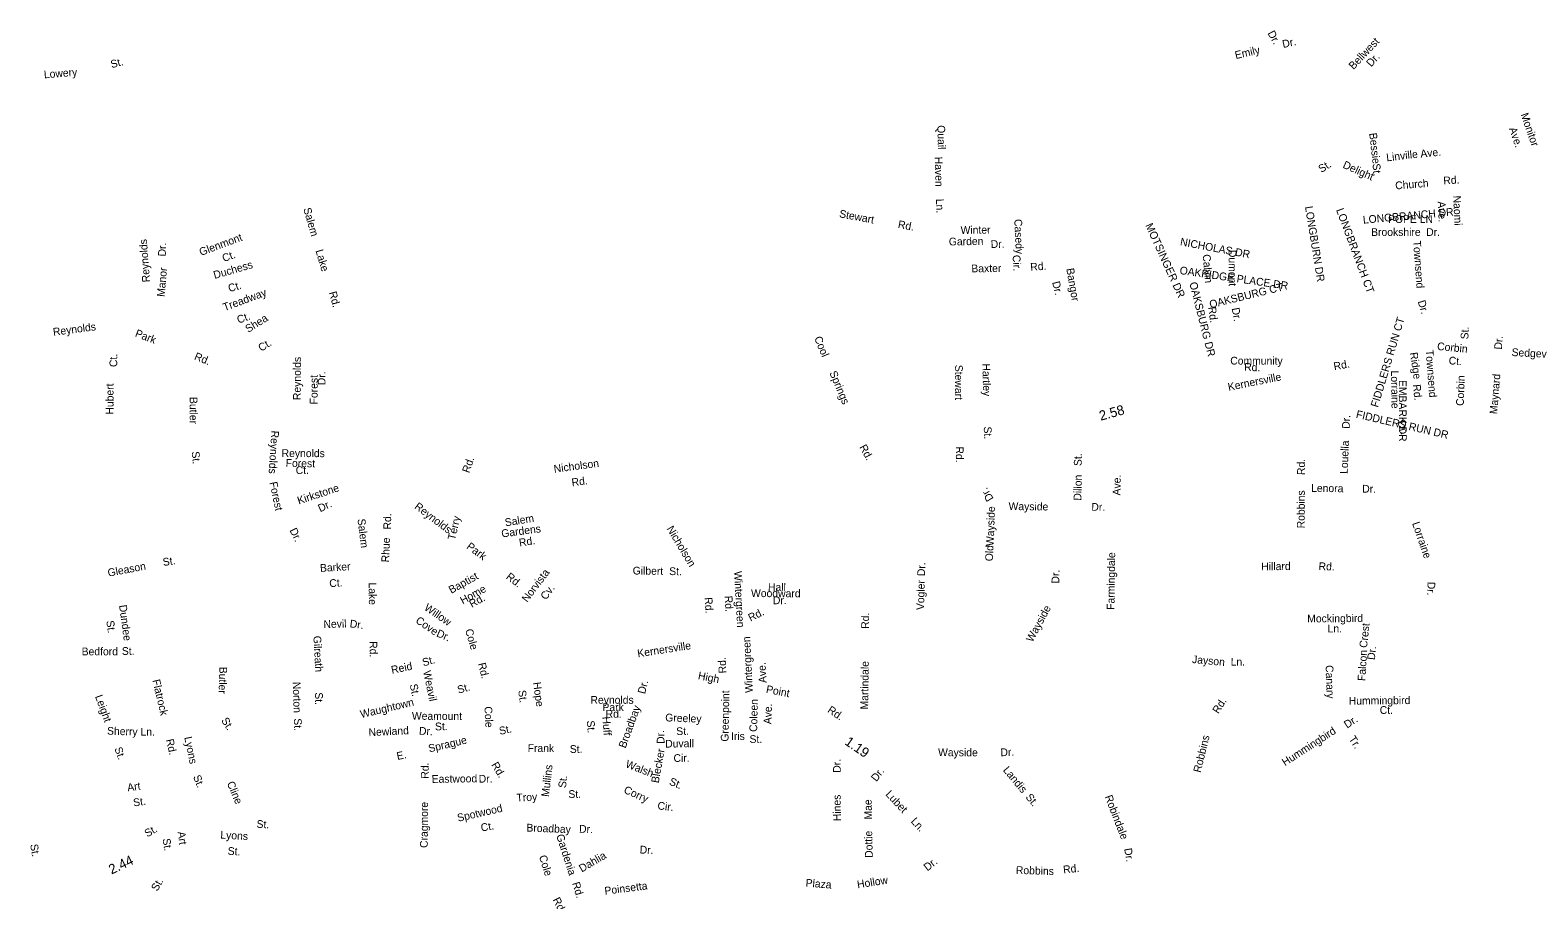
# Model space of a CAD drawing. Extents: x 1553981 to 1780076, y 812965 to 996873.
# Drawn here: x 1644179 to 1662662, y 846092 to 856757 of the extents above; entities that cross this region are included whole.
import ezdxf

# ---------------------------------------------------------------- set-up
doc = ezdxf.new("R2010")
doc.units = 0
for name, color, linetype in [('Exist Road Non-System Type 51 Label', 7, 'Continuous'), ('Exist Road Secondary Mileage Hundredths English Label', 7, 'Continuous'), ('Map Preparation Border Antique Large Shape', 7, 'Continuous')]:
    doc.layers.add(name, color=color, linetype=linetype)

msp = doc.modelspace()

# ---------------------------------------------------------------- texts
at = {"layer": 'Exist Road Non-System Type 51 Label'}
for s, rotation, p in [('Dr.', 299.1057, (1659345, 856720)), ('Bellwest', 46.7145, (1660402, 856267)), ('Emily', 13.3901, (1658960, 856402)), ('Dr.', 12.6518, (1659540, 856538)), ('St.', 15.1558, (1645179, 856290)), ('Dr.', 46.7145, (1660617, 856300)), ('Lowery', 4.3953, (1644351, 856166)), ('Monitor', 289.1936, (1662450, 855723)), ('Quail', 271.5666, (1655300, 855590)), ('Ave.', 289.1936, (1662306, 855549)), ('Bessie', 276.488, (1660594, 855493)), ('Haven', 271.5666, (1655268, 855204)), ('Linville', 6.6442, (1660809, 855148)), ('Ave.', 5.9608, (1661226, 855193)), ('St.', 32.3376, (1660008, 855005)), ('Delight', 335.9415, (1660262, 855073)), ('St.', 274.4838, (1660635, 855119)), ('Church', 4.4507, (1660917, 854804)), ('Rd.', 3.9488, (1661506, 854864)), ('Ln.', 271.4366, (1655284, 854689)), ('Ave.', 272.7401, (1661433, 854656)), ('Naomi', 272.7401, (1661623, 854726)), ('Salem', 286.1221, (1647527, 854566)), ('Stewart', 349.4028, (1654092, 854464)), ('LONGBURN DR', 279.2323, (1659807, 854592)), ('LONGBRANCH CT', 290.4495, (1660187, 854553)), ('LONGBRANCH DR', 5.1687, (1660521, 854384)), ('Glenmont', 20.4825, (1646273, 853988)), ('Rd.', 349.57, (1654812, 854333)), ('Winter', 0.7009, (1655586, 854258)), ('Casedy', 272.7058, (1656243, 854439)), ('MOTSINGER DR', 294.435, (1657848, 854364)), ('Reynolds', 94.2384, (1645649, 853669)), ('Dr.', 88.7513, (1645842, 853982)), ('Lake', 286.2597, (1647677, 854053)), ('Garden', 0.9294, (1655442, 854117)), ('Dr.', 0.9294, (1655955, 854086)), ('NICHOLAS DR', 349.2956, (1658271, 854120)), ('Townsend', 274.2467, (1661132, 854173)), ('Duchess', 16.0045, (1646441, 853706)), ('Ct.', 20.4825, (1646554, 853912)), ('Baxter', 0.8243, (1655718, 853787)), ('Cir.', 272.7058, (1656223, 853999)), ('Rd.', 4.5168, (1656443, 853805)), ('Calvin', 274.8127, (1658553, 854005)), ('Dumont', 270.2794, (1658871, 854062)), ('Manor', 85.0878, (1645827, 853484)), ('Bangor', 279.7543, (1656881, 853831)), ('OAKRIDGE PLACE DR', 351.7144, (1658266, 853768)), ('Treadway', 20.2453, (1646563, 853311)), ('Ct.', 16.0045, (1646622, 853544)), ('Rd.', 285.4459, (1647841, 853540)), ('Dr.', 283.6288, (1656707, 853666)), ('OAKSBURG DR', 284.1943, (1658389, 853656)), ('OAKSBURG CT', 13.7995, (1658648, 853346)), ('Rd.', 277.1788, (1658621, 853360)), ('Dr.', 280.4779, (1658908, 853346)), ('Dr.', 286.8352, (1661188, 853430)), ('Reynolds', 7.4164, (1644465, 853009)), ('Ct.', 20.2453, (1646735, 853157)), ('Shea', 32.1022, (1646853, 853044)), ('FIDDLERS RUN CT', 73.3457, (1660701, 852125)), ('Park', 338.8019, (1645458, 853004)), ('Cool', 292.2326, (1653789, 852981)), ('St.', 87.3854, (1661809, 852964)), ('Dr.', 85.5833, (1662220, 852838)), ('Ct.', 89.9138, (1645247, 852626)), ('Rd.', 337.8544, (1646183, 852722)), ('Ct.', 32.1022, (1647012, 852812)), ('Ridge', 278.24, (1661093, 852801)), ('Townsend', 274.4039, (1661286, 852834)), ('Corbin', 354.5569, (1661424, 852836)), ('Sedgeview', 357.0189, (1662338, 852762)), ('Reynolds', 89.7496, (1647497, 852221)), ('Stewart', 270.1885, (1655517, 852653)), ('Hartley', 271.5171, (1655852, 852669)), ('Community', 359.8326, (1658891, 852657)), ('Rd.', 357.6897, (1659060, 852581)), ('Ct.', 355.4608, (1661566, 852661)), ('Hubert', 89.9138, (1645201, 852043)), ('Forest', 89.5688, (1647702, 852168)), ('Dr.', 89.7496, (1647799, 852403)), ('Springs', 292.7145, (1653975, 852556)), ('Lorraine', 270.8897, (1660861, 852582)), ('EMBARK DR', 270.0698, (1660958, 852467)), ('Rd.', 275.5646, (1661130, 852410)), ('Corbin', 88.0063, (1661753, 852148)), ('Maynard', 85.4047, (1662163, 852046)), ('Butler', 270.1212, (1646135, 852259)), ('FIDDLERS RUN DR', 346.9654, (1660426, 852006)), ('St.', 271.2487, (1655870, 851896)), ('Dr.', 87.1646, (1660354, 851867)), ('Dr.', 286.2023, (1660940, 851951)), ('Reynolds', 266.5153, (1647136, 851849)), ('Rd.', 298.5719, (1654342, 851645)), ('Louella', 87.4387, (1660329, 851314)), ('St.', 275.9137, (1646159, 851587)), ('Reynolds', 359.7813, (1647262, 851523)), ('Forest', 358.7576, (1647311, 851403)), ('Rd.', 70.7489, (1649561, 851320)), ('Rd.', 270.4059, (1655527, 851652)), ('St.', 88.4781, (1657068, 851411)), ('Rd.', 89.8699, (1659806, 851302)), ('Ct.', 0.1469, (1647435, 851314)), ('Nicholson', 7.4942, (1650604, 851330)), ('Dillon', 88.8081, (1657065, 850987)), ('Forest', 281.8689, (1647113, 851210)), ('Kirkstone', 18.4322, (1647473, 850940)), ('Rd.', 7.4942, (1650823, 851163)), ('Dr.', 121.2505, (1655993, 851013)), ('Ave.', 88.7436, (1657544, 851051)), ('Lenora', 359.2183, (1659882, 851096)), ('Dr.', 358.9973, (1660508, 851087)), ('Dr.', 25.1994, (1647735, 850844)), ('Reynolds', 322.7373, (1648882, 850899)), ('Wayside', 359.2922, (1656173, 850873)), ('Dr.', 359.6256, (1657188, 850864)), ('Robbins', 89.6485, (1659803, 850648)), ('Salem', 276.8538, (1648192, 850761)), ('Rd.', 89.6659, (1648604, 850634)), ('Terry', 77.0662, (1649388, 850499)), ('Salem', 9.1181, (1650006, 850672)), ('Wayside', 88.101, (1655991, 850430)), ('Dr.', 296.1869, (1647357, 850625)), ('Gardens', 7.6729, (1649962, 850536)), ('Nicholson', 300.8914, (1651978, 850644)), ('Lorraine', 289.0481, (1661119, 850710)), ('Rhue', 87.8422, (1648579, 850230)), ('Park', 323.2584, (1649520, 850408)), ('Rd.', 9.1181, (1650180, 850424)), ('Old', 87.7848, (1655981, 850243)), ('Gleason', 10.6968, (1645139, 850055)), ('St.', 8.5408, (1645812, 850186)), ('Barker', 3.3079, (1647735, 850114)), ('Dr.', 88.1936, (1655148, 850061)), ('Farmingdale', 89.1883, (1657471, 849648)), ('Hillard', 0.8534, (1659272, 850133)), ('Rd.', 358.2666, (1659973, 850137)), ('Ct.', 3.3079, (1647849, 849927)), ('Baptist', 29.1051, (1649342, 849844)), ('Rd.', 321.8195, (1650005, 850039)), ('Norvista', 53.0207, (1650273, 849734)), ('Gilbert', 359.0484, (1651565, 850083)), ('St.', 358.4875, (1652012, 850076)), ('Wintergreen', 273.1227, (1652808, 850121)), ('Vogler', 88.2703, (1655136, 849645)), ('Dr.', 88.5125, (1656794, 849970)), ('Lake', 270.3446, (1648330, 849984)), ('Home', 29.1051, (1649483, 849714)), ('Rd.', 29.1051, (1649594, 849672)), ('Cv.', 53.0207, (1650502, 849763)), ('Woodward', 359.6514, (1653016, 849806)), ('Hall', 359.6133, (1653224, 849880)), ('Dr.', 266.9195, (1661311, 849995)), ('Dundee', 277.7541, (1645269, 849704)), ('Willow', 325.3378, (1649001, 849655)), ('Rd.', 273.6548, (1652447, 849800)), ('Rd.', 273.1227, (1652693, 849819)), ('Dr.', 0.1557, (1653285, 849718)), ('Wayside', 61.5556, (1656465, 849245)), ('St.', 277.7541, (1645113, 849512)), ('Nevil', 1.3323, (1647776, 849426)), ('Dr.', 352.7805, (1648093, 849435)), ('Cove', 325.3378, (1648896, 849498)), ('Rd.', 89.6636, (1654462, 849416)), ('Mockingbird', 0.4696, (1659835, 849494)), ('Ln.', 0.4696, (1660085, 849371)), ('Crest', 83.889, (1660567, 849179)), ('Gilreath', 273.1485, (1647651, 849328)), ('Dr.', 336.0919, (1649152, 849327)), ('Cole', 286.1781, (1649510, 849401)), ('Wintergreen', 92.8685, (1653040, 848634)), ('Bedford', 0.1217, (1644811, 849091)), ('St.', 0.4943, (1645304, 849096)), ('Rd.', 271.3798, (1648339, 849263)), ('Jayson', 354.7863, (1658420, 848997)), ('Falcon', 86.3822, (1660546, 848774)), ('Dr.', 83.889, (1660663, 849031)), ('Butler', 268.2002, (1646500, 848952)), ('Reid', 11.6135, (1648615, 848864)), ('St.', 15.3194, (1649001, 848955)), ('Weavil', 281.759, (1648996, 848893)), ('Rd.', 283.6979, (1649669, 848989)), ('Rd.', 92.8727, (1652715, 848872)), ('Ave.', 93.0764, (1653207, 848754)), ('Martindale', 89.227, (1654452, 848427)), ('Ln.', 359.7034, (1658896, 848965)), ('Canary', 272.1194, (1660059, 848969)), ('Flatrock', 283.172, (1645677, 848785)), ('Norton', 271.8186, (1647398, 848765)), ('St.', 281.759, (1648832, 848731)), ('Hope', 277.6375, (1650344, 848757)), ('Dr.', 75.427, (1651716, 848611)), ('Leight', 290.2534, (1644973, 848587)), ('St.', 270.4989, (1647672, 848637)), ('St.', 277.6375, (1650162, 848658)), ('Greenpoint', 89.0273, (1652740, 848032)), ('Coleen', 88.4463, (1653090, 848151)), ('Rd.', 56.8319, (1658744, 848368)), ('Hummingbird', 0.5528, (1660344, 848486)), ('Weamount', 359.7403, (1648859, 848301)), ('Cole', 272.8572, (1649748, 848463)), ('Broadbay', 70.1708, (1651478, 847945)), ('Greeley', 357.7293, (1651963, 848282)), ('Ave.', 88.4463, (1653266, 848245)), ('Ct.', 359.8571, (1660723, 848373)), ('Sherry', 358.0748, (1645121, 848119)), ('Ln.', 359.427, (1645532, 848107)), ('St.', 302.1833, (1646518, 848293)), ('St.', 272.1358, (1647412, 848317)), ('Newland', 2.9054, (1648330, 848099)), ('Dr.', 356.8316, (1648944, 848119)), ('St.', 1.0002, (1649143, 848171)), ('St.', 12.5119, (1649939, 848115)), ('St.', 274.1948, (1651003, 848289)), ('Huff', 274.1948, (1651194, 848337)), ('Dr.', 92.2139, (1651957, 848007)), ('St.', 1.9956, (1652101, 848112)), ('Hummingbird', 32.9934, (1659563, 847729)), ('Dr.', 32.9934, (1660323, 848191)), ('Rd.', 282.8308, (1645843, 848055)), ('Lyons', 281.7707, (1646068, 848085)), ('Sprague', 13.4185, (1649073, 847900)), ('Frank', 359.638, (1650278, 847906)), ('St.', 0.712, (1650795, 847894)), ('Duvall', 0.9138, (1651965, 847959)), ('Iris', 0.3524, (1652771, 848052)), ('St.', 0.3524, (1652998, 848016)), ('Robbins', 76.2537, (1658528, 847647)), ('Tr.', 303.3777, (1660339, 848066)), ('St.', 289.3869, (1645211, 847949)), ('E.', 11.4364, (1648682, 847807)), ('Rd.', 300.6326, (1649829, 847749)), ('Walsh', 338.7869, (1651470, 847722)), ('Blecker', 79.8282, (1651884, 847519)), ('Cir.', 0.9138, (1652067, 847783)), ('Dr.', 90.9813, (1654117, 847652)), ('Wayside', 359.7008, (1655309, 847855)), ('Dr.', 2.6615, (1656076, 847853)), ('St.', 291.6477, (1646175, 847603)), ('Rd.', 89.6767, (1649064, 847578)), ('Eastwood', 0.7022, (1649102, 847527)), ('Dr.', 0.4138, (1649678, 847530)), ('Mullins', 83.4384, (1650539, 847352)), ('St.', 83.4384, (1650746, 847460)), ('Dr.', 52.9196, (1654554, 847535)), ('Landis', 309.6995, (1656099, 847681)), ('Art', 8.1361, (1645376, 847422)), ('Cline', 292.6453, (1646589, 847523)), ('St.', 0.5489, (1650778, 847342)), ('Corry', 336.1158, (1651448, 847408)), ('St.', 337.2039, (1652004, 847509)), ('Lubet', 313.2442, (1654658, 847381)), ('St.', 8.1361, (1645449, 847237)), ('Cragmore', 89.668, (1649053, 846729)), ('Spotwood', 12.7904, (1649426, 847050)), ('Troy', 2.683, (1650143, 847298)), ('Cir.', 353.4429, (1651866, 847203)), ('Hines', 90.7865, (1654119, 847058)), ('Mae', 91.6031, (1654501, 847079)), ('St.', 309.418, (1656376, 847349)), ('Robindale', 291.1574, (1657351, 847357)), ('St.', 357.1556, (1646953, 846977)), ('Ln.', 312.6697, (1654969, 847050)), ('Art', 277.9247, (1645987, 846924)), ('Lyons', 356.5416, (1646509, 846845)), ('Ct.', 9.4192, (1649711, 846930)), ('Broadbay', 357.811, (1650262, 846931)), ('Gardenia', 287.7002, (1650627, 846882)), ('Dr.', 357.811, (1650907, 846917)), ('Dottie', 91.4151, (1654509, 846609)), ('St.', 279.804, (1644179, 846769)), ('St.', 277.9247, (1645803, 846840)), ('St.', 356.5416, (1646599, 846646)), ('Dr.', 357.2159, (1651650, 846662)), ('Dr.', 279.7558, (1657590, 846719)), ('Cole', 287.597, (1650415, 846625)), ('Dahlia', 30.5144, (1650942, 846427)), ('Dr.', 38.4868, (1655179, 846440)), ('Robbins', 358.2483, (1656262, 846411)), ('Rd.', 5.8657, (1656847, 846416)), ('St.', 59.3233, (1645737, 846191)), ('Rd.', 287.1216, (1650822, 846296)), ('Plaza', 355.3934, (1653683, 846256)), ('Hollow', 9.1214, (1654324, 846233)), ('Rd.', 296.3618, (1650583, 846095)), ('Poinsetta', 7.2418, (1651226, 846155))]:
    msp.add_text(s, height=95, rotation=rotation, dxfattribs=at).set_placement(p)
for s, p in [('POPE LN', (1660825, 854393)), ('Brookshire', (1660618, 854234)), ('Dr.', (1661293, 854234)), ('Reynolds', (1651048, 848497)), ('Park', (1651195, 848408)), ('Rd.', (1651234, 848326))]:
    msp.add_text(s, height=95, dxfattribs=at).set_placement(p)
at = {"layer": 'Exist Road Secondary Mileage Hundredths English Label'}
for s, rotation, p in [('2.58', 15.4068, (1657303, 851967)), ('1.19', 325.3698, (1654155, 848006)), ('2.44', 25.5931, (1645177, 846402))]:
    msp.add_text(s, height=120, rotation=rotation, dxfattribs=at).set_placement(p)
at = {"layer": 'Map Preparation Border Antique Large Shape'}
for s, rotation, p in [('Rd.', 10.497, (1660167, 852586)), ('Kernersville', 11.4372, (1658872, 852333)), ('Rd.', 26.3831, (1653010, 849503)), ('Kernersville', 8.8477, (1651630, 849066)), ('St.', 15.4986, (1649431, 848620)), ('High', 348.9024, (1652361, 848799)), ('Point', 348.8529, (1653195, 848633)), ('Waughtown', 13.2937, (1648238, 848321)), ('Rd.', 325.7489, (1653945, 848400)), ('St.', 30.246, (1645615, 846857))]:
    msp.add_text(s, height=95, rotation=rotation, dxfattribs=at).set_placement(p)

doc.saveas('drawing.dxf')
